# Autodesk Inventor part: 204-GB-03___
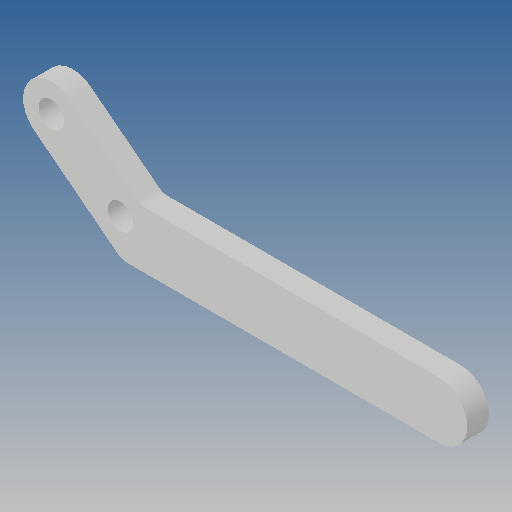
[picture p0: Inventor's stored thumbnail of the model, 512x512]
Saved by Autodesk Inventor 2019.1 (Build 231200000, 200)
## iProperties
Created: 2012-09
Part Number: 204-GB-03___
Material: Ogólny
Document SubType Name: Modeling
Designer: CADENGINEERING4
Density: 1 g/cm^3
Appearance: Domyślna
Author: CADENGINEERING4
Revision Number: ÈÎºÎ
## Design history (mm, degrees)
feature "NONE"
node "Bryła1"
